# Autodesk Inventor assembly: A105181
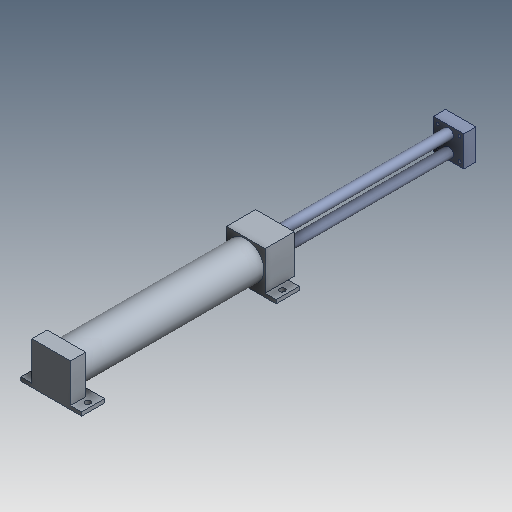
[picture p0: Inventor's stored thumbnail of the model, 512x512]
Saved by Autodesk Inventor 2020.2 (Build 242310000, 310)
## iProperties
Created: 2000-01
Part Number: A105181
Description: CYL,SIDE LUG MNT,SERIES N,2.00X10.5,.62ROD
Document SubType Name: Assembly
Designer: cmcgourin
Mass: 4684.44 g
Surface Area: 1439.23 cm^2
Volume: 1358.45 cm^3
Density: 3.44837 g/cm^3
Control State: 0
Checked Out: False
Master: False
Shininess: 0.0
Length Units: 11269
Angle Units: 11279
Time Units: 11290
Mass Units: 11283
Length Display Precision: 3
Angle Display Precision: 2
Compacted: True
Dimensions: 69,5x673,8x100 mm
Mass: 4,684 kg
Density: 0.0
Volumn: 0.0
Area: 0.0
PropertySet Name: Model Information
Author: cmcgourin
Revision Number: -
Title: CYL,SIDE LUG MNT,SERIES N,2.00X10.5,.62ROD
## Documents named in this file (3)
- D:\07 - DEMODATEN\OTX 2019 - Dataset - UPDATE - Dez2019\Designs\07-Packing machine\A105181.iam
- D:\07 - DEMODATEN\OTX 2019 - Dataset - UPDATE - Dez2019\Designs\07-Packing machine\Parts\ADSK-011798.ipt
- D:\07 - DEMODATEN\OTX 2019 - Dataset - UPDATE - Dez2019\Designs\07-Packing machine\Parts\ADSK-011797.ipt
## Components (2 placed, 2 different names)
1. A105181-001 — Mate:2, Passend:3, Passend:4
2. A105181-002 — Mate:2, Passend:3, Passend:4
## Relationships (3: Mate 3)
- Mate:2: A105181-001 ↔ A105181-002
- Passend:3 [Mate]: A105181-001 ↔ A105181-002
- Passend:4 [Mate]: A105181-001 ↔ A105181-002
